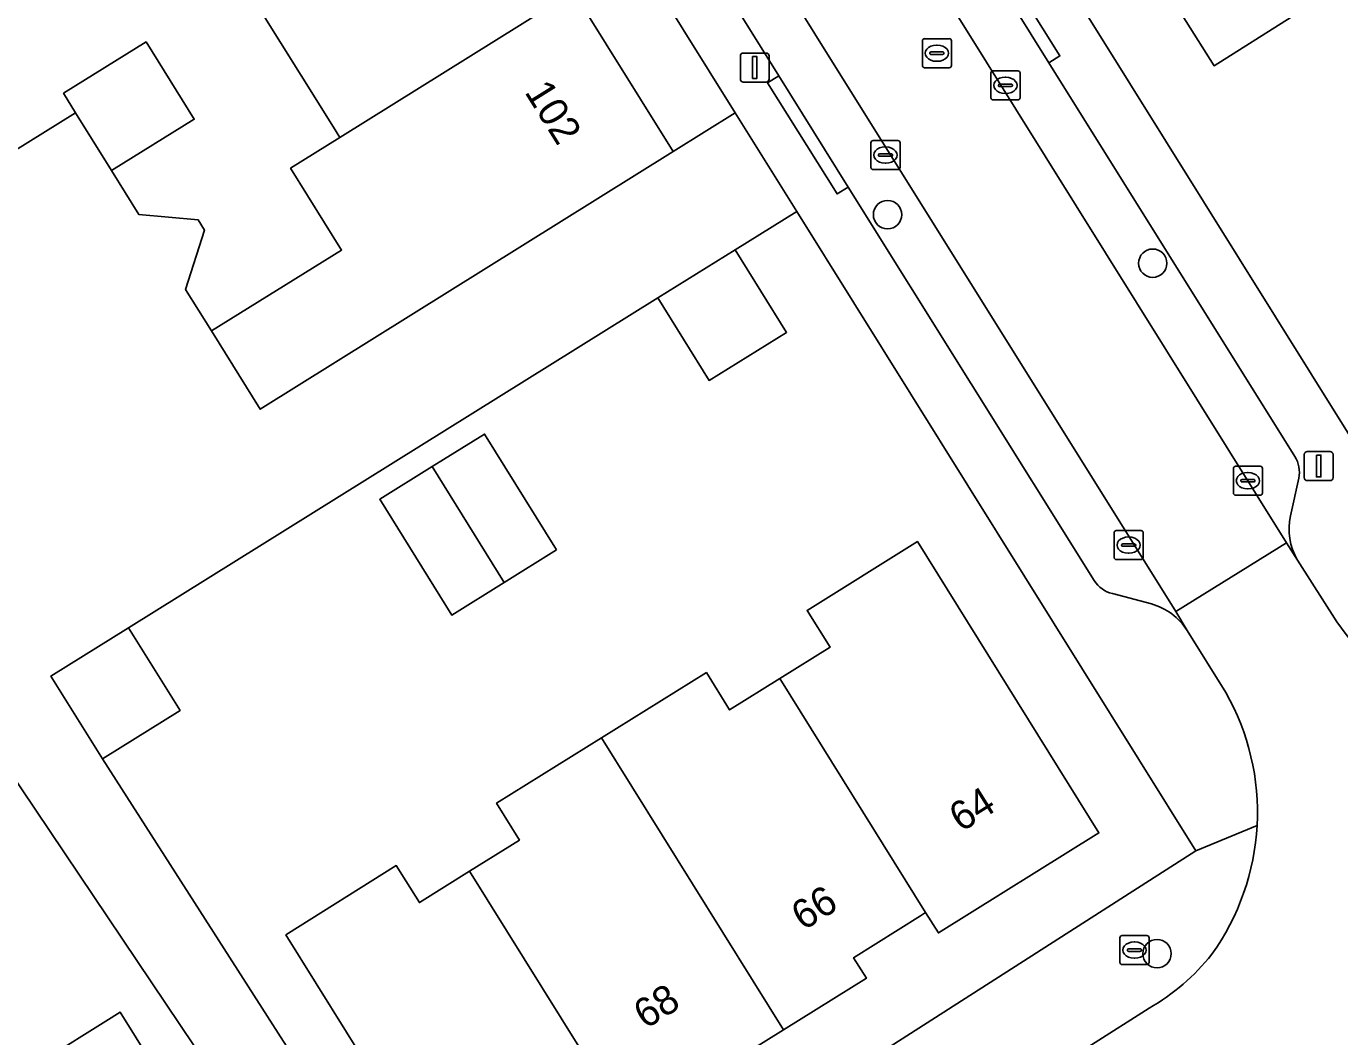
# Model space of a CAD drawing. Extents: x 159664 to 160323, y 385312 to 386115.
# Drawn here: x 159922.18 to 159967.42, y 385550.74 to 385585.55 of the extents above; entities that cross this region are included whole.
import ezdxf

# ---------------------------------------------------------------- set-up
doc = ezdxf.new("R2010")
doc.units = 0
for name, color, linetype in [('IMGEO_Boom', 7, 'Continuous'), ('IMGEO_Brandkraan', 7, 'Continuous'), ('IMGEO_Erf', 7, 'Continuous'), ('IMGEO_Kolk', 7, 'Continuous'), ('IMGEO_Lichtmast', 7, 'Continuous'), ('IMGEO_Pand', 7, 'Continuous'), ('IMGEO_Pand_nummerreeks', 7, 'Continuous'), ('IMGEO_Parkeervlak_open', 7, 'Continuous'), ('IMGEO_Rijbaan_lokaal_open', 7, 'Continuous'), ('IMGEO_Rioolput', 7, 'Continuous'), ('IMGEO_Voetpad_open', 7, 'Continuous')]:
    doc.layers.add(name, color=color, linetype=linetype)

msp = doc.modelspace()

# ---------------------------------------------------------------- linework, layer by layer
at = {"layer": 'IMGEO_Boom'}
for centre in [(159951.848, 385579.055), (159960.982, 385577.383), (159961.13, 385553.6)]:
    msp.add_circle(centre, 0.489, dxfattribs=at)
at = {"layer": 'IMGEO_Brandkraan'}
for p, q in [((159959.928, 385554.222), (159960.78, 385554.222)), ((159959.853, 385553.296), (159959.853, 385554.148)), ((159960.341, 385554.002), (159960.366, 385554.002)), ((159960.854, 385554.148), (159960.854, 385553.296)), ((159960.112, 385553.716), (159960.112, 385553.728)), ((159960.55, 385553.679), (159960.152, 385553.679)), ((159960.155, 385553.765), (159960.553, 385553.765)), ((159960.364, 385553.442), (159960.339, 385553.442)), ((159960.596, 385553.728), (159960.596, 385553.716)), ((159960.78, 385553.222), (159959.928, 385553.222))]:
    msp.add_line(p, q, dxfattribs=at)
for points in [[(159959.928, 385554.222), (159960.78, 385554.222)], [(159959.853, 385553.296), (159959.853, 385554.148)], [(159960.854, 385554.148), (159960.854, 385553.296)], [(159960.78, 385553.222), (159959.928, 385553.222)]]:
    msp.add_lwpolyline(points, dxfattribs=at)
for centre, radius, start, end in [((159959.93, 385554.146), 0.0765, 91.552, 178.448), ((159959.93, 385554.146), 0.0765, 91.552, 178.448), ((159960.778, 385554.146), 0.0765, 1.552, 88.448), ((159960.778, 385554.146), 0.0765, 1.552, 88.448), ((159960.557, 385553.727), 0.0386, 1.7309, 96.639), ((159960.152, 385553.725), 0.0403, 85.8775, 175.7526), ((159960.149, 385553.715), 0.0366, 178.938, 274.7102), ((159960.553, 385553.722), 0.043, 264.8664, 352.4533), ((159959.93, 385553.298), 0.0765, 181.552, 268.448), ((159959.93, 385553.298), 0.0765, 181.552, 268.448), ((159960.778, 385553.298), 0.0765, 271.552, 358.448), ((159960.778, 385553.298), 0.0765, 271.552, 358.448)]:
    msp.add_arc(centre, radius, start, end, dxfattribs=at)
for centre, major_axis, ratio, start_param, end_param in [((159960.34, 385553.722), (-0.387, 0.002), 0.722429, 4.712389, 7.853982), ((159960.365, 385553.722), (-0.39, 0.002), 0.717154, 1.570796, 4.712389)]:
    msp.add_ellipse(centre, major_axis=major_axis, ratio=ratio, start_param=start_param, end_param=end_param, dxfattribs=at)
at = {"layer": 'IMGEO_Erf'}
for points in [[(159941.035, 385586.738), (159944.465, 385581.237), (159946.596, 385582.567), (159899.669, 385657.765)], [(159958.955, 385585.56), (159972.712, 385563.525), (160021.079, 385593.612)], [(159965.748, 385585.857), (159963.094, 385584.187), (159961.311, 385587.031)], [(159913.324, 385585.901), (159913.918, 385583.625), (159913.343, 385582.866), (159913.805, 385580.841), (159916.645, 385582.603), (159918.314, 385579.947), (159915.464, 385578.171), (159915.839, 385577.568), (159923.882, 385582.567), (159923.464, 385583.24), (159926.31, 385585.008), (159927.966, 385582.342), (159925.121, 385580.574), (159926.058, 385579.067), (159928.104, 385578.877), (159928.317, 385578.524), (159927.671, 385576.481), (159928.558, 385575.051), (159933.042, 385577.833), (159931.285, 385580.654), (159932.981, 385581.712), (159932.854, 385581.915), (159932.417, 385582.616), (159930.17, 385586.219)], [(159930.483, 385546.685), (159918.508, 385564.491), (159915.634, 385568.765), (159890.065, 385552.798), (159891.585, 385550.364), (159906.565, 385526.327)], [(159937.39, 385544.189), (159931.123, 385554.245), (159934.923, 385556.631), (159935.72, 385555.36), (159937.446, 385556.437), (159939.17, 385557.512), (159938.378, 385558.786), (159941.996, 385561.035), (159945.611, 385563.283), (159946.404, 385561.994), (159948.136, 385563.074), (159949.866, 385564.152), (159949.073, 385565.425), (159952.875, 385567.795), (159959.13, 385557.761), (159953.599, 385554.312), (159953.159, 385555.017), (159952.981, 385554.905), (159950.678, 385553.458), (159951.117, 385552.753), (159948.266, 385550.978), (159945.405, 385549.196)]]:
    msp.add_lwpolyline(points, dxfattribs=at)
for points in [[(159948.717, 385579.169), (159946.6, 385577.848), (159948.369, 385575), (159945.702, 385573.343), (159943.933, 385576.192), (159925.703, 385564.826), (159927.477, 385561.979), (159924.806, 385560.315), (159937.201, 385540.961), (159962.464, 385557.14)], [(159940.448, 385567.509), (159938.642, 385566.386), (159936.836, 385565.263), (159934.355, 385569.252), (159936.161, 385570.375), (159937.967, 385571.498)], [(159922.867, 385549.989), (159924.924, 385551.271), (159925.418, 385551.579), (159927.123, 385548.842), (159924.572, 385547.252)]]:
    msp.add_lwpolyline(points, close=True, dxfattribs=at)
at = {"layer": 'IMGEO_Kolk'}
for p, q in [((159955.409, 385583.084), (159955.409, 385583.936)), ((159955.484, 385584.01), (159956.336, 385584.01)), ((159955.897, 385583.79), (159955.922, 385583.79)), ((159956.41, 385583.936), (159956.41, 385583.084)), ((159955.668, 385583.504), (159955.668, 385583.516)), ((159956.106, 385583.467), (159955.708, 385583.467)), ((159955.711, 385583.553), (159956.109, 385583.553)), ((159955.92, 385583.23), (159955.895, 385583.23)), ((159956.152, 385583.516), (159956.152, 385583.504)), ((159956.336, 385583.01), (159955.484, 385583.01)), ((159951.276, 385580.683), (159951.276, 385581.535)), ((159951.351, 385581.609), (159952.203, 385581.609)), ((159951.764, 385581.389), (159951.789, 385581.389)), ((159952.277, 385581.535), (159952.277, 385580.683)), ((159951.535, 385581.103), (159951.535, 385581.115)), ((159951.973, 385581.066), (159951.575, 385581.066)), ((159951.578, 385581.152), (159951.976, 385581.152)), ((159952.019, 385581.115), (159952.019, 385581.103)), ((159952.203, 385580.609), (159951.351, 385580.609)), ((159951.787, 385580.829), (159951.762, 385580.829)), ((159963.76, 385569.465), (159963.76, 385570.317)), ((159963.835, 385570.391), (159964.687, 385570.391)), ((159964.248, 385570.171), (159964.273, 385570.171)), ((159964.761, 385570.317), (159964.761, 385569.465)), ((159964.019, 385569.885), (159964.019, 385569.897)), ((159964.457, 385569.848), (159964.059, 385569.848)), ((159964.062, 385569.934), (159964.46, 385569.934)), ((159964.271, 385569.611), (159964.246, 385569.611)), ((159964.503, 385569.897), (159964.503, 385569.885)), ((159964.687, 385569.391), (159963.835, 385569.391)), ((159959.651, 385567.248), (159959.651, 385568.1)), ((159959.726, 385568.174), (159960.578, 385568.174)), ((159960.139, 385567.954), (159960.164, 385567.954)), ((159960.652, 385568.1), (159960.652, 385567.248)), ((159959.91, 385567.668), (159959.91, 385567.68)), ((159960.348, 385567.631), (159959.95, 385567.631)), ((159959.953, 385567.717), (159960.351, 385567.717)), ((159960.162, 385567.394), (159960.137, 385567.394)), ((159960.394, 385567.68), (159960.394, 385567.668)), ((159960.578, 385567.174), (159959.726, 385567.174))]:
    msp.add_line(p, q, dxfattribs=at)
for points in [[(159955.409, 385583.084), (159955.409, 385583.936)], [(159955.484, 385584.01), (159956.336, 385584.01)], [(159956.41, 385583.936), (159956.41, 385583.084)], [(159956.336, 385583.01), (159955.484, 385583.01)], [(159951.276, 385580.683), (159951.276, 385581.535)], [(159951.351, 385581.609), (159952.203, 385581.609)], [(159952.277, 385581.535), (159952.277, 385580.683)], [(159952.203, 385580.609), (159951.351, 385580.609)], [(159963.76, 385569.465), (159963.76, 385570.317)], [(159963.835, 385570.391), (159964.687, 385570.391)], [(159964.761, 385570.317), (159964.761, 385569.465)], [(159964.687, 385569.391), (159963.835, 385569.391)], [(159959.651, 385567.248), (159959.651, 385568.1)], [(159959.726, 385568.174), (159960.578, 385568.174)], [(159960.652, 385568.1), (159960.652, 385567.248)], [(159960.578, 385567.174), (159959.726, 385567.174)]]:
    msp.add_lwpolyline(points, dxfattribs=at)
for centre, radius, start, end in [((159955.486, 385583.934), 0.0765, 91.552, 178.448), ((159955.486, 385583.934), 0.0765, 91.552, 178.448), ((159956.334, 385583.934), 0.0765, 1.552, 88.448), ((159956.334, 385583.934), 0.0765, 1.552, 88.448), ((159955.708, 385583.513), 0.0403, 85.8775, 175.7526), ((159955.705, 385583.503), 0.0366, 178.938, 274.7102), ((159956.109, 385583.51), 0.043, 264.8664, 352.4533), ((159956.113, 385583.515), 0.0386, 1.7309, 96.639), ((159955.486, 385583.086), 0.0765, 181.552, 268.448), ((159955.486, 385583.086), 0.0765, 181.552, 268.448), ((159956.334, 385583.086), 0.0765, 271.552, 358.448), ((159956.334, 385583.086), 0.0765, 271.552, 358.448), ((159951.353, 385581.533), 0.0765, 91.552, 178.448), ((159951.353, 385581.533), 0.0765, 91.552, 178.448), ((159952.201, 385581.533), 0.0765, 1.552, 88.448), ((159952.201, 385581.533), 0.0765, 1.552, 88.448), ((159951.575, 385581.112), 0.0403, 85.8775, 175.7526), ((159951.572, 385581.102), 0.0366, 178.938, 274.7102), ((159951.976, 385581.109), 0.043, 264.8664, 352.4533), ((159951.98, 385581.114), 0.0386, 1.7309, 96.639), ((159951.353, 385580.685), 0.0765, 181.552, 268.448), ((159951.353, 385580.685), 0.0765, 181.552, 268.448), ((159952.201, 385580.685), 0.0765, 271.552, 358.448), ((159952.201, 385580.685), 0.0765, 271.552, 358.448), ((159963.837, 385570.315), 0.0765, 91.552, 178.448), ((159963.837, 385570.315), 0.0765, 91.552, 178.448), ((159964.685, 385570.315), 0.0765, 1.552, 88.448), ((159964.685, 385570.315), 0.0765, 1.552, 88.448), ((159964.059, 385569.894), 0.0403, 85.8775, 175.7526), ((159964.056, 385569.884), 0.0366, 178.938, 274.7102), ((159964.46, 385569.891), 0.043, 264.8664, 352.4533), ((159964.464, 385569.896), 0.0386, 1.7309, 96.639), ((159963.837, 385569.467), 0.0765, 181.552, 268.448), ((159963.837, 385569.467), 0.0765, 181.552, 268.448), ((159964.685, 385569.467), 0.0765, 271.552, 358.448), ((159964.685, 385569.467), 0.0765, 271.552, 358.448), ((159959.728, 385568.098), 0.0765, 91.552, 178.448), ((159959.728, 385568.098), 0.0765, 91.552, 178.448), ((159960.576, 385568.098), 0.0765, 1.552, 88.448), ((159960.576, 385568.098), 0.0765, 1.552, 88.448), ((159959.95, 385567.677), 0.0403, 85.8775, 175.7526), ((159959.947, 385567.667), 0.0366, 178.938, 274.7102), ((159960.351, 385567.674), 0.043, 264.8664, 352.4533), ((159960.355, 385567.679), 0.0386, 1.7309, 96.639), ((159959.728, 385567.25), 0.0765, 181.552, 268.448), ((159959.728, 385567.25), 0.0765, 181.552, 268.448), ((159960.576, 385567.25), 0.0765, 271.552, 358.448), ((159960.576, 385567.25), 0.0765, 271.552, 358.448)]:
    msp.add_arc(centre, radius, start, end, dxfattribs=at)
for centre, major_axis, ratio, start_param, end_param in [((159955.896, 385583.51), (-0.387, 0.002), 0.722429, 4.712389, 7.853982), ((159955.921, 385583.51), (-0.39, 0.002), 0.717154, 1.570796, 4.712389), ((159951.763, 385581.109), (-0.387, 0.002), 0.722429, 4.712389, 7.853982), ((159951.788, 385581.109), (-0.39, 0.002), 0.717154, 1.570796, 4.712389), ((159964.247, 385569.891), (-0.387, 0.002), 0.722429, 4.712389, 7.853982), ((159964.272, 385569.891), (-0.39, 0.002), 0.717154, 1.570796, 4.712389), ((159960.138, 385567.674), (-0.387, 0.002), 0.722429, 4.712389, 7.853982), ((159960.163, 385567.674), (-0.39, 0.002), 0.717154, 1.570796, 4.712389)]:
    msp.add_ellipse(centre, major_axis=major_axis, ratio=ratio, start_param=start_param, end_param=end_param, dxfattribs=at)
at = {"layer": 'IMGEO_Lichtmast'}
for p, q in [((159946.877, 385584.624), (159947.667, 385584.624)), ((159947.667, 385584.624), (159946.877, 385584.624)), ((159946.777, 385583.724), (159946.777, 385584.524)), ((159946.777, 385584.524), (159946.777, 385583.724)), ((159947.767, 385584.524), (159947.767, 385583.724)), ((159947.767, 385583.724), (159947.767, 385584.524)), ((159947.667, 385583.624), (159946.877, 385583.624)), ((159946.877, 385583.624), (159947.667, 385583.624)), ((159966.202, 385569.996), (159966.202, 385570.796)), ((159966.202, 385570.796), (159966.202, 385569.996)), ((159966.302, 385570.896), (159967.092, 385570.896)), ((159967.092, 385570.896), (159966.302, 385570.896)), ((159967.192, 385570.796), (159967.192, 385569.996)), ((159967.192, 385569.996), (159967.192, 385570.796)), ((159967.092, 385569.896), (159966.302, 385569.896)), ((159966.302, 385569.896), (159967.092, 385569.896))]:
    msp.add_line(p, q, dxfattribs=at)
for points in [[(159947.197, 385584.499), (159947.347, 385584.499), (159947.347, 385583.749), (159947.197, 385583.749), (159947.197, 385584.499)], [(159966.622, 385570.771), (159966.772, 385570.771), (159966.772, 385570.021), (159966.622, 385570.021), (159966.622, 385570.771)]]:
    msp.add_lwpolyline(points, dxfattribs=at)
for centre, start, end in [((159946.877, 385584.524), 90, 180), ((159946.877, 385584.524), 90, 180), ((159947.667, 385584.524), 0, 90), ((159947.667, 385584.524), 360, 90), ((159946.877, 385583.724), 180, 270), ((159946.877, 385583.724), 180, 270), ((159947.667, 385583.724), 270, 0), ((159947.667, 385583.724), 270, 0), ((159966.302, 385570.796), 90, 180), ((159966.302, 385570.796), 90, 180), ((159967.092, 385570.796), 0, 90), ((159967.092, 385570.796), 360, 90), ((159966.302, 385569.996), 180, 270), ((159966.302, 385569.996), 180, 270), ((159967.092, 385569.996), 270, 0), ((159967.092, 385569.996), 270, 0)]:
    msp.add_arc(centre, 0.1, start, end, dxfattribs=at)
at = {"layer": 'IMGEO_Pand'}
for points in [[(159937.792, 385591.941), (159937.718, 385592.06), (159929.662, 385587.033), (159929.753, 385586.887), (159930.17, 385586.219), (159932.417, 385582.616), (159932.854, 385581.915), (159932.981, 385581.712), (159941.035, 385586.738)], [(159965.748, 385585.857), (159963.979, 385588.716), (159961.311, 385587.031), (159963.094, 385584.187)], [(159944.465, 385581.237), (159941.035, 385586.738), (159932.981, 385581.712), (159931.285, 385580.654), (159933.042, 385577.833), (159928.558, 385575.051), (159930.238, 385572.355)], [(159926.31, 385585.008), (159923.464, 385583.24), (159923.882, 385582.567), (159925.121, 385580.574), (159927.966, 385582.342)], [(159948.369, 385575), (159946.6, 385577.848), (159943.933, 385576.192), (159945.702, 385573.343)], [(159940.448, 385567.509), (159937.967, 385571.498), (159936.161, 385570.375), (159938.642, 385566.386)], [(159938.642, 385566.386), (159936.161, 385570.375), (159934.355, 385569.252), (159936.836, 385565.263)], [(159952.875, 385567.795), (159949.073, 385565.425), (159949.866, 385564.152), (159948.136, 385563.074), (159953.159, 385555.017), (159953.599, 385554.312), (159959.13, 385557.761)], [(159927.477, 385561.979), (159925.703, 385564.826), (159923.032, 385563.162), (159924.806, 385560.315)], [(159948.136, 385563.074), (159946.404, 385561.994), (159945.611, 385563.283), (159941.996, 385561.035), (159948.266, 385550.978), (159951.117, 385552.753), (159950.678, 385553.458), (159952.981, 385554.905), (159953.159, 385555.017)], [(159941.996, 385561.035), (159938.378, 385558.786), (159939.17, 385557.512), (159937.446, 385556.437), (159942.485, 385548.354), (159942.659, 385548.462), (159944.966, 385549.9), (159945.405, 385549.196), (159948.266, 385550.978)], [(159937.446, 385556.437), (159935.72, 385555.36), (159934.923, 385556.631), (159931.123, 385554.245), (159937.39, 385544.189), (159942.924, 385547.649), (159942.485, 385548.354)], [(159922.867, 385549.989), (159924.572, 385547.252), (159927.123, 385548.842), (159925.418, 385551.579), (159924.924, 385551.271)]]:
    msp.add_lwpolyline(points, close=True, dxfattribs=at)
at = {"layer": 'IMGEO_Parkeervlak_open'}
for points in [[(159962.17, 385564.73), (159961.779, 385565.383), (159924.478, 385625.1), (159922.547, 385628.192), (159899.375, 385665.288), (159889.146, 385681.776), (159876.656, 385701.792), (159875.092, 385700.818), (159884.424, 385685.806), (159898.925, 385662.608), (159901.313, 385658.777), (159948.098, 385583.838), (159950.488, 385580), (159958.964, 385566.45)], [(159893.484, 385683.297), (159926.401, 385630.553), (159928.296, 385627.517), (159965.594, 385567.755), (159965.967, 385567.159)], [(159965.875, 385570.728), (159957.4, 385584.281), (159955.023, 385588.111), (159908.276, 385663), (159905.898, 385666.829), (159896.695, 385681.58)], [(159965.728, 385568.678), (159966.008, 385569.975)], [(159959.591, 385566), (159960.939, 385565.644)]]:
    msp.add_lwpolyline(points, dxfattribs=at)
for centre, radius, start, end in [((159965.053, 385570.195), 0.98, 347.0464, 32.9869), ((159967.772, 385568.221), 2.094, 167.4026, 210.4807), ((159959.846, 385567.018), 1.049, 212.7574, 255.9083), ((159960.355, 385563.572), 2.153, 32.5488, 74.2645)]:
    msp.add_arc(centre, radius, start, end, dxfattribs=at)
at = {"layer": 'IMGEO_Rijbaan_lokaal_open'}
msp.add_lwpolyline([(159928.296, 385627.517), (159924.478, 385625.1), (159961.779, 385565.383), (159965.594, 385567.755)], close=True, dxfattribs=at)
for points in [[(159967.323, 385565.032), (159965.967, 385567.159), (159965.594, 385567.755), (159961.779, 385565.383), (159962.17, 385564.73), (159963.498, 385562.595)], [(159960.856, 385551.72), (159958.877, 385550.463), (159961.421, 385546.425), (159983.092, 385560.012), (159980.628, 385563.98)]]:
    msp.add_lwpolyline(points, dxfattribs=at)
for centre, radius, start, end in [((159974.114, 385569.634), 8.203, 214.1234, 244.7056), ((159956.218, 385558.463), 8.371, 356.9341, 29.579), ((159956.223, 385558.463), 8.365, 324.2651, 356.9319), ((159957.138, 385558.223), 7.491, 299.7576, 321.6676)]:
    msp.add_arc(centre, radius, start, end, dxfattribs=at)
at = {"layer": 'IMGEO_Rioolput'}
for p, q in [((159953.046, 385584.192), (159953.046, 385585.044)), ((159953.121, 385585.118), (159953.973, 385585.118)), ((159954.047, 385585.044), (159954.047, 385584.192)), ((159953.305, 385584.612), (159953.305, 385584.624)), ((159953.743, 385584.575), (159953.345, 385584.575)), ((159953.348, 385584.661), (159953.746, 385584.661)), ((159953.534, 385584.898), (159953.559, 385584.898)), ((159953.789, 385584.624), (159953.789, 385584.612)), ((159953.973, 385584.118), (159953.121, 385584.118)), ((159953.557, 385584.338), (159953.532, 385584.338))]:
    msp.add_line(p, q, dxfattribs=at)
for points in [[(159953.046, 385584.192), (159953.046, 385585.044)], [(159953.121, 385585.118), (159953.973, 385585.118)], [(159954.047, 385585.044), (159954.047, 385584.192)], [(159953.973, 385584.118), (159953.121, 385584.118)]]:
    msp.add_lwpolyline(points, dxfattribs=at)
for centre, radius, start, end in [((159953.123, 385585.042), 0.0765, 91.552, 178.448), ((159953.123, 385585.042), 0.0765, 91.552, 178.448), ((159953.971, 385585.042), 0.0765, 1.552, 88.448), ((159953.971, 385585.042), 0.0765, 1.552, 88.448), ((159953.345, 385584.621), 0.0403, 85.8775, 175.7526), ((159953.342, 385584.611), 0.0366, 178.938, 274.7102), ((159953.746, 385584.618), 0.043, 264.8664, 352.4533), ((159953.75, 385584.623), 0.0386, 1.7309, 96.639), ((159953.123, 385584.194), 0.0765, 181.552, 268.448), ((159953.123, 385584.194), 0.0765, 181.552, 268.448), ((159953.971, 385584.194), 0.0765, 271.552, 358.448), ((159953.971, 385584.194), 0.0765, 271.552, 358.448)]:
    msp.add_arc(centre, radius, start, end, dxfattribs=at)
for centre, major_axis, ratio, start_param, end_param in [((159953.533, 385584.618), (-0.387, 0.002), 0.722429, 4.712389, 7.853982), ((159953.558, 385584.618), (-0.39, 0.002), 0.717154, 1.570796, 4.712389)]:
    msp.add_ellipse(centre, major_axis=major_axis, ratio=ratio, start_param=start_param, end_param=end_param, dxfattribs=at)
at = {"layer": 'IMGEO_Voetpad_open'}
for points in [[(159870.48, 385704.729), (159868.229, 385703.363), (159879.357, 385685.561), (159879.997, 385685.936), (159882.47, 385682.008), (159884.023, 385682.836), (159897.553, 385661.156), (159899.669, 385657.765), (159946.596, 385582.567), (159948.717, 385579.169), (159962.464, 385557.14), (159964.577, 385558.015)], [(159958.964, 385566.45), (159950.488, 385580), (159950.108, 385579.772), (159947.714, 385583.597), (159948.098, 385583.838), (159901.313, 385658.777), (159900.929, 385658.558), (159898.546, 385662.389), (159898.925, 385662.608), (159884.424, 385685.806), (159875.092, 385700.818)], [(159970.609, 385562.217), (159972.712, 385563.525), (159958.955, 385585.56), (159956.838, 385588.951), (159909.89, 385664.146), (159907.72, 385667.621), (159893.04, 385691.134)], [(159896.695, 385681.58), (159905.898, 385666.829), (159906.281, 385667.07), (159908.661, 385663.245), (159908.276, 385663), (159955.023, 385588.111), (159955.397, 385588.346), (159957.782, 385584.525), (159957.4, 385584.281), (159965.875, 385570.728)], [(159918.508, 385564.491), (159930.483, 385546.685), (159932.814, 385542.953), (159932.775, 385542.929), (159934.995, 385539.548), (159937.201, 385540.961), (159924.806, 385560.315), (159923.032, 385563.162), (159925.703, 385564.826), (159943.933, 385576.192), (159946.6, 385577.848), (159948.717, 385579.169), (159946.596, 385582.567), (159944.465, 385581.237), (159930.238, 385572.355), (159928.558, 385575.051), (159927.671, 385576.481), (159928.317, 385578.524), (159928.104, 385578.877), (159926.058, 385579.067), (159925.121, 385580.574), (159923.882, 385582.567), (159915.839, 385577.568)], [(159966.008, 385569.975), (159965.728, 385568.678)], [(159965.967, 385567.159), (159967.323, 385565.032)], [(159960.939, 385565.644), (159959.591, 385566)], [(159963.498, 385562.595), (159962.17, 385564.73)], [(159964.577, 385558.015), (159962.464, 385557.14), (159937.201, 385540.961), (159934.995, 385539.548), (159931.692, 385537.54), (159911.749, 385525.069)], [(159958.652, 385550.323), (159958.877, 385550.463), (159960.856, 385551.72)]]:
    msp.add_lwpolyline(points, dxfattribs=at)
for points in [[(159955.023, 385588.111), (159957.4, 385584.281), (159957.782, 385584.525), (159955.397, 385588.346)], [(159948.098, 385583.838), (159947.714, 385583.597), (159950.108, 385579.772), (159950.488, 385580)]]:
    msp.add_lwpolyline(points, close=True, dxfattribs=at)
for centre, radius, start, end in [((159965.053, 385570.195), 0.98, 347.0464, 32.9869), ((159967.772, 385568.221), 2.094, 167.4026, 210.4807), ((159959.846, 385567.018), 1.049, 212.7574, 255.9083), ((159960.355, 385563.572), 2.153, 32.5488, 74.2645), ((159974.114, 385569.634), 8.203, 214.1234, 244.7056), ((159956.218, 385558.463), 8.371, 356.9341, 29.579), ((159956.223, 385558.463), 8.365, 324.2651, 356.9319), ((159957.138, 385558.223), 7.491, 299.7576, 321.6676)]:
    msp.add_arc(centre, radius, start, end, dxfattribs=at)

# ---------------------------------------------------------------- texts
at = {"layer": 'IMGEO_Pand_nummerreeks'}
for s, rotation, p in [('102', 301.9651, (159939.325, 385583.281)), ('64', 31.9768, (159954.381, 385557.767)), ('66', 31.9768, (159948.945, 385554.373)), ('68', 31.9768, (159943.512, 385550.982))]:
    msp.add_text(s, height=1, rotation=rotation, dxfattribs=at).set_placement(p)

doc.saveas('drawing.dxf')
